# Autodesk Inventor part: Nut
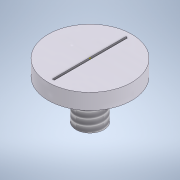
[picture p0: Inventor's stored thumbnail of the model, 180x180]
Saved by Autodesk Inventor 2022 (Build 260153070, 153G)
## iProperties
Created: 2021-06
Part Number: Nut
Material: Aluminum 6061, Welded
Document SubType Name: Modeling
Designer: Administrator
Density: 2.7 g/cm^3
Appearance: Weld - Aluminum
Author: Administrator
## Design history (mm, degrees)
sketch "Sketch1"
  geometry: 1 further point
sketch "Sketch2"
  geometry: C1 r 2.703 at (0, 0); 1 further point
  constraints: 1 centre point, 1 coincident
  dimensions: "d8" = 5.40626 diameter of C1
extrude "Extrusion1" new body sketch "Sketch2" distance "d0" = 1.016; taper "d1" = 0 deg
sketch "Sketch3"
  geometry: C1 r 0.905 at (0, 0); 1 further point
  constraints: 1 centre point, 1 coincident
  dimensions: "d9" = 1.81007 diameter of C1
extrude "Extrusion2" join sketch "Sketch3" distance "d2" = 2.54; taper "d3" = 0 deg
thread "Thread1" dims "d4" = 2.54, "d5" = 0
sketch "Sketch4"
  geometry: L1 (-0.055, 2.398)-(-0.055, -2.39); L2 (-0.055, -2.39)-(0.075, -2.39); L3 (0.075, -2.39)-(0.075, 2.34); L4 (0.075, 2.34)-(-0.055, 2.398); 1 further point
  constraints: 8 end point, 1 parallel, 1 perpendicular, 1 vertical
extrude "Extrusion3" cut sketch "Sketch4" distance "d6" = 0.381; taper "d7" = 0 deg
body "Solid1"
